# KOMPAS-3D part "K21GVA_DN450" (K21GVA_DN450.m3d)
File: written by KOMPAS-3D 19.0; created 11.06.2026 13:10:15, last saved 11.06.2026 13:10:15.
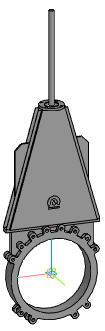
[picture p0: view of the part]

Document properties: Автор: Энергия; Полное имя файла: Z:\3.Личные\kachalov\001_3d для проектировщиков\2.5 Тип_K21GVA. Задвижка\_stp\_stp_K21GVA_DN50-DN1000_с фланцем\K21GVA_DN450.m3d

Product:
- Part/product: K21GVA_DN450

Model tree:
1. Операция без истории:1  (labels: K21GVA_DN450)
